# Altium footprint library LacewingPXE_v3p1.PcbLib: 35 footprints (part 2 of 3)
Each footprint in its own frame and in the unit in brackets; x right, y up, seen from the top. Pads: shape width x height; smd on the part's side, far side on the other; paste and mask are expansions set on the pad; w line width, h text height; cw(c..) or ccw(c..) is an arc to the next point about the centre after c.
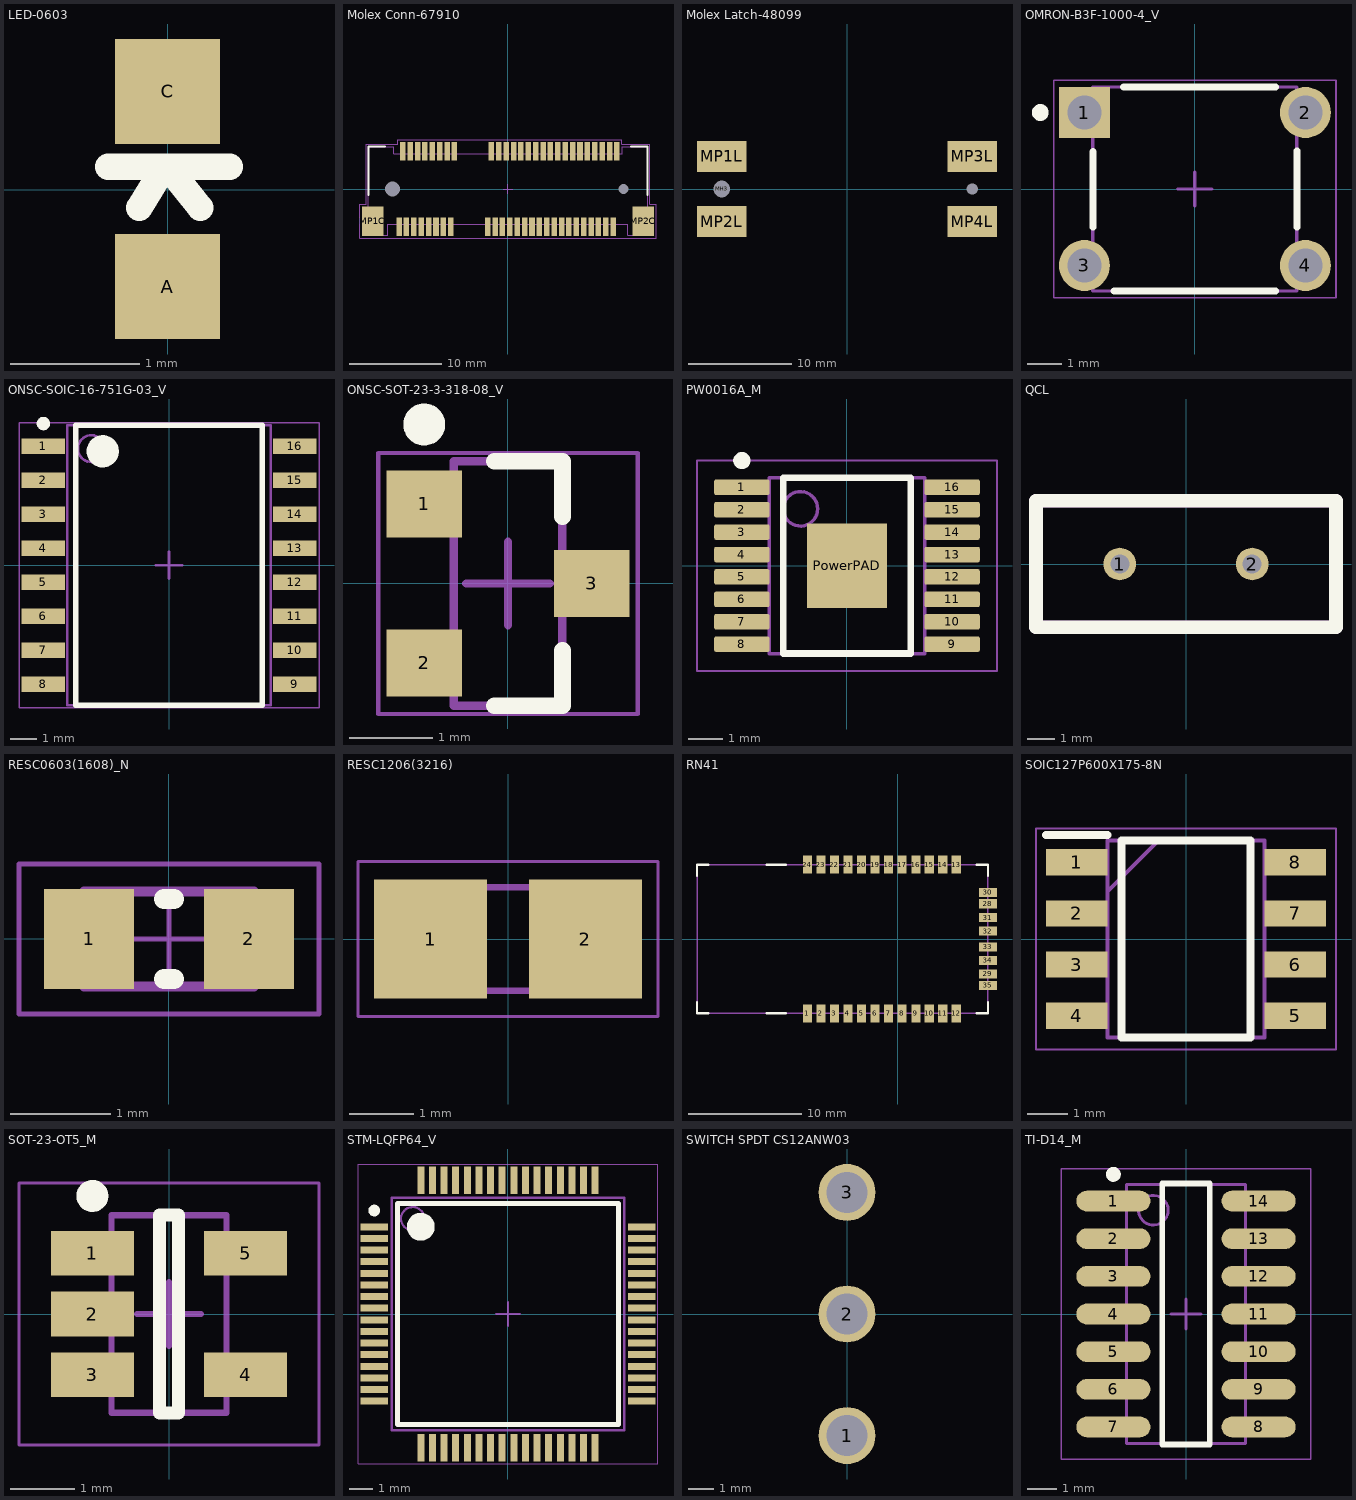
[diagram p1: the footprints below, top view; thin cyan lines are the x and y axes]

## LED-0603 [mil] "LED-0603"
pads (2):
  rect 32x32 smd: A(0,-29.53) C(0,30)
Top Overlay:
  lines w8: -18.11,7 0,7 ; -8.6,-5.51 -1,7 ; 10,-5.51 0,7 ; 19,7 0,7

## Molex Conn-67910 [mm] "Board-to-Board Connector, SMT, Right Angle, Pitch 0.8mm, 52-Position, Female"
pads (56):
  rect 0.6x2 smd: 1(-11.8,-4.1) 2(-11.4,4.1) 3(-11,-4.1) 4(-10.6,4.1) 5(-10.2,-4.1) 6(-9.8,4.1) 7(-9.4,-4.1) 8(-9,4.1) 9(-8.6,-4.1) 10(-8.2,4.1) 11(-7.8,-4.1) 12(-7.4,4.1) 13(-7,-4.1) 14(-6.6,4.1) 15(-6.2,-4.1) 16(-5.8,4.1) 17(-2.2,-4.1) 18(-1.8,4.1) 19(-1.4,-4.1) 20(-1,4.1) 21(-0.6,-4.1) 22(-0.2,4.1) 23(0.2,-4.1) 24(0.6,4.1) 25(1,-4.1) 26(1.4,4.1) 27(1.8,-4.1) 28(2.2,4.1) 29(2.6,-4.1) 30(3,4.1) 31(3.4,-4.1) 32(3.8,4.1) 33(4.2,-4.1) 34(4.6,4.1) 35(5,-4.1) 36(5.4,4.1) 37(5.8,-4.1) 38(6.2,4.1) 39(6.6,-4.1) 40(7,4.1) 41(7.4,-4.1) 42(7.8,4.1) 43(8.2,-4.1) 44(8.6,4.1) 45(9,-4.1) 46(9.4,4.1) 47(9.8,-4.1) 48(10.2,4.1) 49(10.6,-4.1) 50(11,4.1) 51(11.4,-4.1) 52(11.8,4.1)
  round 1.3 hole 1.6 unplated: MH1(-12.5,0)
  round 0.8 hole 1.1 unplated: MH2(12.5,0)
  rect 2.3x3.2 smd: MP1C(-14.65,-3.5) MP2C(14.65,-3.5)
Top Overlay:
  lines w0.2: -15.125,-0.633 -15.125,4.6 -14.907,4.6 -13.338,4.6 ; 13.329,4.6 15.125,4.6 ; 15.125,-0.645 15.125,4.535
Mechanical 13:
  lines w0.1: -15.125,-3.8 -14.025,-3.8 ; -15.125,-3.798 -15.125,4.6 -14.907,4.6 -12.375,4.6 -12.375,3.799 ; -14.027,-5 -13,-5 -13,-3.8 13,-3.8 13,-5 14.01,-5 14.025,-4.985 14.025,-3.804 ; -14.025,-5 -14.025,-3.822 ; -12.375,3.8 12.375,3.8 12.375,4.601 ; 12.375,4.6 15.125,4.6 15.125,4.535 15.125,-3.796 ; 14.025,-3.8 15.125,-3.8
Mechanical 15:
  lines w0.1: -0.5,0 0.5,0 ; 0,-0.5 0,0.5 ; -16.05,-5.35 16.05,-5.35 16.05,-1.65 15.375,-1.65 15.375,4.85 12.35,4.85 12.35,5.35 -11.95,5.35 -11.95,4.85 -15.375,4.85 -15.375,-1.65 -16.05,-1.65 -16.05,-5.35
3D body: height 0.82, standoff 0.2, extent 12.35,3.8 15,4.5
3D body: height 0.82, standoff 0.2, extent 15,4.5 15,4.5
3D body: height 0.82, standoff 0.2, extent -15,3.7 -12.35,4.5
3D body: height 1.34, standoff 0.69, extent 12.1,-4.25 13.79,-3.7
3D body: height 1.34, standoff 0.69, extent -13.79,-4.25 -12.1,-3.7
3D body: height 5.6, standoff 4.54, extent -13.79,-5 -12.1,-3.7
3D body: height 5.6, standoff 4.54, extent 12.1,-5 13.79,-3.7
3D body: height 5.6, standoff 3.12, extent -15,-3.7 15,3.677
3D body: height 3.12, standoff 0, extent -15,-3.7 15,3.8

## Molex Latch-48099 [mm]
pads (6):
  round 1.3 hole 1.6 unplated: MH3(-12.1,0)
  round 0.8 hole 1.1 unplated: MH4(12.1,0)
  rect 4.8x3 smd: MP1L(-12.1,3.15) MP2L(-12.1,-3.15) MP3L(12.1,3.15) MP4L(12.1,-3.15)

## OMRON-B3F-1000-4_V [mm] "TH, 4-Leads, Body 6x6mm"
height 4.5
pads (4):
  rect 1.5x1.5 hole 1 paste+0: 1(-3.25,2.25)
  round 1.5 hole 1 paste+0: 2(3.25,2.25) 3(-3.25,-2.25) 4(3.25,-2.25)
Top Overlay:
  circle w0.25: c-4.55,2.25 r0.125
  lines w0.2: -3,-1.127 -3,1.1 ; -2.378,-3 2.378,-3 ; -2.1,3 2.378,3 ; 3,-1.127 3,1.127
Mechanical 13:
  lines w0.1: -3,-3 -3,3 3,3 3,-3 -3,-3
Mechanical 15:
  lines w0.05: -4.15,-3.2 -4.15,3.2 4.15,3.2 4.15,-3.2 -4.15,-3.2
  lines w0.1: -0.5,0 0.5,0 ; 0,-0.5 0,0.5
3D body: height 4.5, standoff 0, extent -3,-3 3,3

## ONSC-SOIC-16-751G-03_V [mm] "SOIC, 16-Leads, Body 10.45x7.6mm, Pitch 1.27mm"
height 2.65
pads (16):
  rect 1.62x0.58 smd: 1(-4.69,4.445) 2(-4.69,3.175) 3(-4.69,1.905) 4(-4.69,0.635) 5(-4.69,-0.635) 6(-4.69,-1.905) 7(-4.69,-3.175) 8(-4.69,-4.445) 9(4.69,-4.445) 10(4.69,-3.175) 11(4.69,-1.905) 12(4.69,-0.635) 13(4.69,0.635) 14(4.69,1.905) 15(4.69,3.175) 16(4.69,4.445)
Top Overlay:
  circle w0.25: c-4.69,5.285 r0.125
  circle w0.6: c-2.475,4.25 r0.3
  lines w0.2: -3.48,-5.225 -3.48,5.225 3.48,5.225 3.48,-5.225 -3.48,-5.225
Mechanical 13:
  circle w0.1: c-2.9,4.35 r0.5
  lines w0.1: -3.8,-5.225 -3.8,5.225 3.8,5.225 3.8,-5.225 -3.8,-5.225
Mechanical 15:
  lines w0.05: -5.6,-5.325 -5.6,5.325 5.6,5.325 5.6,-5.325 -5.6,-5.325
  lines w0.1: -0.5,0 0.5,0 ; 0,-0.5 0,0.5
3D body: height 2.65, standoff 0.1, extent -3.8,-5.225 3.8,5.225

## ONSC-SOT-23-3-318-08_V [mm] "SOT23, 3-Leads, Body 2.92x1.3mm, Pitch 0.95mm"
height 1.11
pads (3):
  rect 0.9x0.8 smd: 1(-1,0.95) 2(-1,-0.95) 3(1,0)
Top Overlay:
  circle w0.25: c-1,1.9 r0.125
  lines w0.2: -0.165,-1.46 0.65,-1.46 0.65,-0.8 ; -0.165,1.46 0.65,1.46 0.65,0.8
Mechanical 13:
  lines w0.1: -0.65,-1.46 0.65,-1.46 0.65,1.46 -0.65,1.46 -0.65,-1.46
Mechanical 15:
  lines w0.05: -1.55,-1.56 1.55,-1.56 1.55,1.56 -1.55,1.56 -1.55,-1.56
  lines w0.1: -0.5,0 0.5,0 ; 0,-0.5 0,0.5
3D body: height 1.11, standoff 0.01, extent -0.65,-1.46 0.65,1.46

## PW0016A_M [mm] "SOP, 16-Leads, Body 5.1x4.5mm, Pitch 0.65mm, IPC Low Density"
height 1.2
pads (17):
  rrect22% 1.6x0.45 smd: 1(-3.05,2.275) 2(-3.05,1.625) 3(-3.05,0.975) 4(-3.05,0.325) 5(-3.05,-0.325) 6(-3.05,-0.975) 7(-3.05,-1.625) 8(-3.05,-2.275) 9(3.05,-2.275) 10(3.05,-1.625) 11(3.05,-0.975) 12(3.05,-0.325) 13(3.05,0.325) 14(3.05,0.975) 15(3.05,1.625) 16(3.05,2.275)
  rect 2.31x2.46 smd: PowerPAD(0,0)
Top Overlay:
  circle w0.25: c-3.05,3.05 r0.125
  lines w0.2: -1.85,-2.55 -1.85,2.55 1.85,2.55 1.85,-2.55 -1.85,-2.55
Mechanical 13:
  circle w0.1: c-1.35,1.65 r0.5
  lines w0.1: -2.25,-2.55 -2.25,2.55 2.25,2.55 2.25,-2.55 -2.25,-2.55
Mechanical 15:
  lines w0.05: -4.35,-3.05 -4.35,3.05 4.35,3.05 4.35,-3.05 -4.35,-3.05
  lines w0.1: -0.5,0 0.5,0 ; 0,-0.5 0,0.5
3D body "PW0016AakaMTC16.stp": height 1, standoff 0, extent -3.21,-2.5 3.21,2.5

## QCL [mm]
pads (2):
  round 1.2 hole 0.7: 1(-2.44,0) 2(2.44,0)
Top Overlay:
  lines w0.5: -5.525,-2.325 -5.525,2.325 5.525,2.325 5.525,-2.325 -5.525,-2.325
Mechanical 15:
  lines w0.5: -5.525,-2.325 5.525,-2.325 5.525,2.325 -5.525,2.325 -5.525,-2.325

## RESC0603(1608)_N [mm] "Chip Resistor, Body 1.6x0.8mm, IPC Medium Density"
height 0.6
pads (2):
  rect 0.9x1 smd: 1(-0.8,0) 2(0.8,0)
Top Overlay:
  lines w0.2: -0.05,-0.4 0.05,-0.4 ; -0.05,0.4 0.05,0.4
Mechanical 13:
  lines w0.1: -0.85,-0.475 0.85,-0.475 0.85,0.475 -0.85,0.475 -0.85,-0.475
Mechanical 15:
  lines w0.05: -0.475,0 0.475,0 ; 0,-0.475 0,0.475 ; -1.5,-0.75 1.5,-0.75 1.5,0.75 -1.5,0.75 -1.5,-0.75
3D body: height 0.6, standoff 0, extent -0.849,-0.474 -0.58,0.475
3D body: height 0.6, standoff 0, extent -0.58,-0.474 0.581,0.475
3D body: height 0.6, standoff 0, extent 0.581,-0.474 0.85,0.475

## RESC1206(3216) [mm]
pads (2):
  rect 1.75x1.85 smd: 1(-1.2,0) 2(1.2,0)
Mechanical 13:
  lines w0.1: -1.6,-0.8 -1.6,0.8 1.6,0.8 1.6,-0.8 -1.6,-0.8
Mechanical 15:
  lines w0.05: -2.325,-1.2 -2.325,1.2 2.325,1.2 2.325,-1.2 -2.325,-1.2
3D body "WSLP12061L000FEA.stp": height 0.89, standoff 0, extent -1.6,-0.8 1.6,0.8

## RN41 [mil]
pads (32):
  rect 32x63 smd: 1(-315.42,-259.92) 2(-268.18,-259.92) 3(-220.93,-259.92) 4(-173.69,-259.92) 5(-126.44,-259.92) 6(-79.2,-259.92) 7(-31.58,-259.92) 8(15.42,-259.92) 9(63.42,-259.92) 10(110.42,-259.92) 11(157.42,-259.92) 12(204.42,-259.92) 13(204.42,259.92) 14(157.42,259.92) 15(110.42,259.92) 16(63.42,259.92) 17(15.42,259.92) 18(-31.58,259.92) 19(-79.2,259.92) 20(-126.44,259.92) 21(-173.69,259.92) 22(-220.93,259.92) 23(-268.18,259.92) 24(-315.42,259.92)
  rect 63x32 smd: 28(315.42,122.92) 29(315.42,-122.13) 30(315.42,162.92) 31(315.42,74.92) 32(315.42,27.92) 33(315.42,-27.64) 34(315.42,-74.88) 35(315.42,-162.37)
Top Overlay:
  lines w8: -701.25,-220.55 -701.25,-259.92 -661.88,-259.92 ; -701.25,220.92 -701.25,259.92 -661.88,259.92 ; -457.15,-259.92 -390.22,-259.92 ; -457.15,259.92 -390.22,259.92 ; 275.42,-259.92 315.42,-259.92 315.42,-220.55 ; 275.42,259.92 315.42,259.92 315.42,220.92
Mechanical 16:
  lines w5: -701.25,-259.92 315.42,-259.92 315.42,259.92 -701.25,259.92 -701.25,-259.92

## SOIC127P600X175-8N [mm]
pads (8):
  rect 1.525x0.65 smd: 1(-2.712,1.905) 2(-2.712,0.635) 3(-2.712,-0.635) 4(-2.712,-1.905) 5(2.712,-1.905) 6(2.712,-0.635) 7(2.712,0.635) 8(2.712,1.905)
Top Overlay:
  lines w0.2: -3.475,2.58 -1.95,2.58 ; -1.6,-2.45 1.6,-2.45 1.6,2.45 -1.6,2.45 -1.6,-2.45
Mechanical 13:
  lines w0.1: -1.95,1.18 -0.68,2.45 ; -1.95,-2.45 1.95,-2.45 1.95,2.45 -1.95,2.45 -1.95,-2.45
Mechanical 15:
  lines w0.05: -3.725,-2.75 3.725,-2.75 3.725,2.75 -3.725,2.75 -3.725,-2.75
3D body "NE555DR.stp": height 1.75, standoff 0, extent -3,-2.45 3,2.45

## SOT-23-OT5_M [mm] "SOT23, 5-Leads, Body 2.9x1.7mm, Pitch 0.95mm, Lead Span 2.8mm, IPC Low Density"
height 1.45
pads (5):
  rect 1.3x0.7 smd: 1(-1.2,0.95) 2(-1.2,0) 3(-1.2,-0.95) 4(1.2,-0.95) 5(1.2,0.95)
Top Overlay:
  circle w0.25: c-1.2,1.85 r0.125
  lines w0.2: -0.15,-1.55 -0.15,1.55 0.15,1.55 0.15,-1.55 -0.15,-1.55
Mechanical 13:
  lines w0.1: -0.9,-1.55 0.9,-1.55 0.9,1.55 -0.9,1.55 -0.9,-1.55
Mechanical 15:
  lines w0.05: -2.35,-2.05 2.35,-2.05 2.35,2.05 -2.35,2.05 -2.35,-2.05
  lines w0.1: -0.5,0 0.5,0 ; 0,-0.5 0,0.5
3D body: height 1.45, standoff 0, extent -0.9,-1.55 0.9,1.55

## STM-LQFP64_V [mm] "Thin QFP, 64-Leads, Body 10x10mm, Pitch 0.5mm, ST Recommended"
height 1.6
pads (64):
  rect 1.2x0.3 smd: 1(-5.75,3.75) 2(-5.75,3.25) 3(-5.75,2.75) 4(-5.75,2.25) 5(-5.75,1.75) 6(-5.75,1.25) 7(-5.75,0.75) 8(-5.75,0.25) 9(-5.75,-0.25) 10(-5.75,-0.75) 11(-5.75,-1.25) 12(-5.75,-1.75) 13(-5.75,-2.25) 14(-5.75,-2.75) 15(-5.75,-3.25) 16(-5.75,-3.75) 33(5.75,-3.75) 34(5.75,-3.25) 35(5.75,-2.75) 36(5.75,-2.25) 37(5.75,-1.75) 38(5.75,-1.25) 39(5.75,-0.75) 40(5.75,-0.25) 41(5.75,0.25) 42(5.75,0.75) 43(5.75,1.25) 44(5.75,1.75) 45(5.75,2.25) 46(5.75,2.75) 47(5.75,3.25) 48(5.75,3.75)
  rect 0.3x1.2 smd: 17(-3.75,-5.75) 18(-3.25,-5.75) 19(-2.75,-5.75) 20(-2.25,-5.75) 21(-1.75,-5.75) 22(-1.25,-5.75) 23(-0.75,-5.75) 24(-0.25,-5.75) 25(0.25,-5.75) 26(0.75,-5.75) 27(1.25,-5.75) 28(1.75,-5.75) 29(2.25,-5.75) 30(2.75,-5.75) 31(3.25,-5.75) 32(3.75,-5.75) 49(3.75,5.75) 50(3.25,5.75) 51(2.75,5.75) 52(2.25,5.75) 53(1.75,5.75) 54(1.25,5.75) 55(0.75,5.75) 56(0.25,5.75) 57(-0.25,5.75) 58(-0.75,5.75) 59(-1.25,5.75) 60(-1.75,5.75) 61(-2.25,5.75) 62(-2.75,5.75) 63(-3.25,5.75) 64(-3.75,5.75)
Top Overlay:
  circle w0.25: c-5.75,4.45 r0.125
  circle w0.6: c-3.75,3.75 r0.3
  lines w0.2: -4.75,-4.75 -4.75,4.75 4.75,4.75 4.75,-4.75 -4.75,-4.75
Mechanical 13:
  circle w0.1: c-4.1,4.1 r0.5
  lines w0.1: -5,-5 -5,5 5,5 5,-5 -5,-5
Mechanical 15:
  lines w0.05: -6.45,-6.45 -6.45,6.45 6.45,6.45 6.45,-6.45 -6.45,-6.45
  lines w0.1: -0.5,0 0.5,0 ; 0,-0.5 0,0.5
3D body: height 1.6, standoff 0.05, extent -5,-5 5,5

## SWITCH SPDT CS12ANW03 [mm]
pads (3):
  round 2.2 hole 1.6: 1(0,-4.7) 2(0,0) 3(0,4.7)

## TI-D14_M [mm] "SOIC, 14-Leads, Body 8.65x3.9mm, Pitch 1.27mm, IPC Low Density"
height 1.75
pads (14):
  oval 2.5x0.7 smd: 1(-2.45,3.81) 2(-2.45,2.54) 3(-2.45,1.27) 4(-2.45,0) 5(-2.45,-1.27) 6(-2.45,-2.54) 7(-2.45,-3.81) 8(2.45,-3.81) 9(2.45,-2.54) 10(2.45,-1.27) 11(2.45,0) 12(2.45,1.27) 13(2.45,2.54) 14(2.45,3.81)
Top Overlay:
  circle w0.25: c-2.45,4.71 r0.125
  lines w0.2: -0.8,-4.4 -0.8,4.4 0.8,4.4 0.8,-4.4 -0.8,-4.4
Mechanical 13:
  circle w0.1: c-1.1,3.5 r0.5
  lines w0.1: -2,-4.375 -2,4.375 2,4.375 2,-4.375 -2,-4.375
Mechanical 15:
  lines w0.05: -4.2,-4.9 -4.2,4.9 4.2,4.9 4.2,-4.9 -4.2,-4.9
  lines w0.1: -0.5,0 0.5,0 ; 0,-0.5 0,0.5
3D body: height 1.75, standoff 0.1, extent -2,-4.375 2,4.375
